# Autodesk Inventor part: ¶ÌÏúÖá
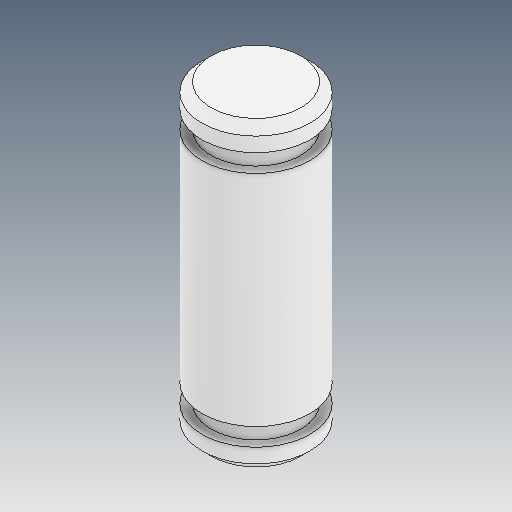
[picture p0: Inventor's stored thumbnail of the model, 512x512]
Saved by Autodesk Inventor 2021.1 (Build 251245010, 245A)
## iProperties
Created: 2021-06
Part Number: ¶ÌÏúÖá
Material: Ogólny
Document SubType Name: Modeling
Designer: user
Density: 1 g/cm^3
Appearance: Domyślna
Author: user
Revision Number: ÈÎºÎ
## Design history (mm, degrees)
feature "Ðý×ª1"
node "Bryła1"
